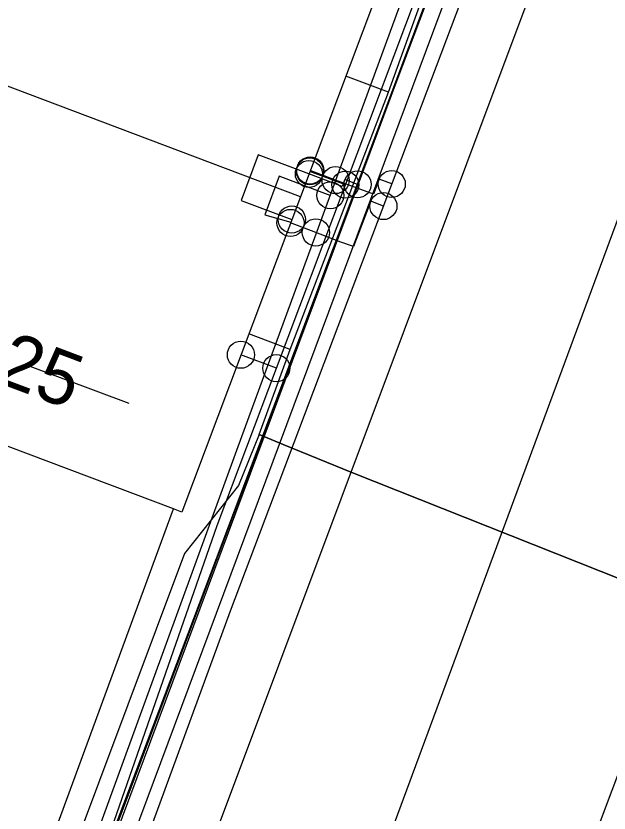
# Model space of a CAD drawing. Extents: x 192672 to 192910, y 446344 to 446512.
# Drawn here: x 192741.13 to 192752.08, y 446417.71 to 446432.42 of the extents above; entities that cross this region are included whole.
import ezdxf

# ---------------------------------------------------------------- set-up
doc = ezdxf.new("R2010")
doc.units = 0
for name, color, linetype in [('B-OI-KL-()_PUNTVANLEVERING_WATER-S', 7, 'Continuous'), ('B-OI-KL-BUISLEIDING_OLIEGASCHEMICALIEN_GASLAGEDRUK-G', 7, 'Continuous'), ('B-OI-KL-DATA-G', 7, 'Continuous'), ('B-OI-KL-DATA_GTWP-S', 7, 'Continuous'), ('B-OI-KL-DATA_KABELBED-G', 7, 'Continuous'), ('B-OI-KL-DATA_MANTELBUIS-G', 7, 'Continuous'), ('B-OI-KL-DATA_MOF-S', 7, 'Continuous'), ('B-OI-KL-ET_LS-G', 7, 'Continuous'), ('B-OI-KL-ET_LS_DELIVERYPOINT-S', 7, 'Continuous'), ('B-OI-KL-ET_LS_MOF-S', 7, 'Continuous'), ('B-OI-KL-GAS_LD_AFTAKZADEL-S', 7, 'Continuous'), ('B-OI-KL-GAS_LD_DELIVERYPOINT-S', 7, 'Continuous'), ('B-OI-KL-GAS_LD_OVERGANGSSTUK-S', 7, 'Continuous'), ('B-OI-KL-WATER-G', 7, 'Continuous'), ('B-OI-RI-RIOOLVRIJVERVAL-G', 7, 'Continuous'), ('Default', 7, 'Continuous'), ('huisnummerreeks BGT', 7, 'Continuous'), ('kant open verharding', 7, 'Continuous'), ('kant verharding', 7, 'Continuous'), ('pand op maaiveld vlak', 7, 'Continuous')]:
    doc.layers.add(name, color=color, linetype=linetype)

# ---------------------------------------------------------------- blocks, each defined once
blk = doc.blocks.new('B-OI-KL-GAS_LD_AFTAKZADEL-S')
at = {"layer": 'Default'}
blk.add_circle((0, 0), 0.25, dxfattribs=at)
blk = doc.blocks.new('B-OI-KL-GAS_LD_DELIVERYPOINT-S')
at = {"layer": 'Default'}
blk.add_circle((0, 0), 0.25, dxfattribs=at)
blk = doc.blocks.new('B-OI-KL-GAS_LD_OVERGANGSSTUK-S')
at = {"layer": 'Default'}
blk.add_circle((0, 0), 0.25, dxfattribs=at)
blk = doc.blocks.new('B-OI-KL-ET_LS_DELIVERYPOINT-S')
at = {"layer": 'Default'}
blk.add_circle((0, 0), 0.25, dxfattribs=at)
blk = doc.blocks.new('B-OI-KL-ET_LS_MOF-S')
at = {"layer": 'Default'}
blk.add_circle((0, 0), 0.25, dxfattribs=at)
blk = doc.blocks.new('B-OI-KL-()_PUNTVANLEVERING_WATER-S')
at = {"layer": 'Default'}
blk.add_circle((0, 0), 0.25, dxfattribs=at)
blk = doc.blocks.new('B-OI-KL-DATA_GTWP-S')
at = {"layer": 'Default'}
blk.add_circle((0, 0), 0.25, dxfattribs=at)
blk = doc.blocks.new('B-OI-KL-DATA_MOF-S')
at = {"layer": 'Default'}
blk.add_circle((0, 0), 0.25, dxfattribs=at)

msp = doc.modelspace()

# ---------------------------------------------------------------- linework, layer by layer
at = {"layer": 'B-OI-KL-BUISLEIDING_OLIEGASCHEMICALIEN_GASLAGEDRUK-G'}
for points in [[(192770.261, 446499.113), (192771.393, 446496.803), (192772.556, 446494.554), (192770.877, 446489.886), (192758.67, 446457.345), (192745.084, 446421.436), (192742.217, 446413.618)], [(192747.03, 446429.391), (192746.562, 446429.568)], [(192748.067, 446429.32), (192747.833, 446429.409), (192747.727, 446429.129), (192747.03, 446429.391)], [(192747.913, 446428.912), (192747.679, 446429.001), (192747.362, 446428.163), (192747.125, 446428.244), (192746.666, 446428.425)], [(192746.666, 446428.425), (192746.198, 446428.601)]]:
    msp.add_lwpolyline(points, dxfattribs=at)
at = {"layer": 'B-OI-KL-DATA-G'}
for points in [[(192768.74, 446486.807), (192749.794, 446435.599), (192742.072, 446415.039), (192739.06, 446406.841), (192720.2, 446413.77), (192719.012, 446414.118), (192696.077, 446422.823), (192683.193, 446427.673), (192678.122, 446429.261), (192675.743, 446430.156)], [(192768.74, 446486.807), (192749.794, 446435.599), (192742.072, 446415.039), (192739.06, 446406.841), (192738.917, 446406.249), (192738.75, 446405.758), (192738.438, 446405.088), (192738.002, 446404.406), (192737.543, 446403.858), (192737.067, 446403.408), (192736.56, 446403.025), (192736.06, 446402.723), (192733.684, 446396.245), (192734.518, 446394.712), (192730.316, 446383.423), (192727.316, 446375.697), (192722.899, 446364.033), (192722.458, 446362.715), (192718.077, 446351.086), (192716.68, 446347.404), (192715.968, 446345.556)], [(192768.74, 446486.807), (192749.794, 446435.599), (192742.072, 446415.039), (192739.06, 446406.841), (192738.917, 446406.249), (192738.75, 446405.758), (192738.438, 446405.088), (192738.002, 446404.406), (192737.543, 446403.858), (192737.067, 446403.408), (192736.56, 446403.025), (192736.06, 446402.723), (192733.684, 446396.245), (192734.518, 446394.712), (192730.316, 446383.423), (192727.316, 446375.697), (192722.899, 446364.033), (192722.458, 446362.715), (192718.077, 446351.086), (192716.68, 446347.404), (192715.968, 446345.556)], [(192768.74, 446486.807), (192749.794, 446435.599), (192742.072, 446415.039), (192739.06, 446406.841), (192738.917, 446406.249), (192738.75, 446405.758), (192738.438, 446405.088), (192738.002, 446404.406), (192737.543, 446403.858), (192737.067, 446403.408), (192736.56, 446403.025), (192736.06, 446402.723), (192733.684, 446396.245), (192734.518, 446394.712), (192730.316, 446383.423), (192727.316, 446375.697), (192722.899, 446364.033), (192722.458, 446362.715), (192718.077, 446351.086), (192716.68, 446347.404), (192715.968, 446345.556)], [(192768.74, 446486.807), (192749.794, 446435.599), (192742.072, 446415.039), (192739.06, 446406.841), (192738.917, 446406.249), (192738.75, 446405.758), (192738.438, 446405.088), (192738.002, 446404.406), (192737.543, 446403.858), (192737.067, 446403.408), (192736.56, 446403.025), (192736.06, 446402.723), (192733.684, 446396.245), (192734.518, 446394.712), (192730.316, 446383.423), (192727.316, 446375.697), (192722.899, 446364.033), (192722.458, 446362.715), (192718.077, 446351.086), (192716.68, 446347.404), (192715.968, 446345.556)], [(192768.74, 446486.807), (192749.794, 446435.599), (192742.072, 446415.039), (192739.06, 446406.841), (192738.917, 446406.249), (192738.75, 446405.758), (192738.438, 446405.088), (192738.002, 446404.406), (192737.543, 446403.858), (192737.067, 446403.408), (192736.56, 446403.025), (192736.06, 446402.723), (192733.684, 446396.245), (192734.518, 446394.712), (192730.316, 446383.423), (192727.316, 446375.697), (192722.899, 446364.033), (192722.458, 446362.715), (192718.077, 446351.086), (192716.68, 446347.404), (192715.968, 446345.556)], [(192768.74, 446486.807), (192749.794, 446435.599), (192742.072, 446415.039), (192739.06, 446406.841), (192738.917, 446406.249), (192738.75, 446405.758), (192738.438, 446405.088), (192738.002, 446404.406), (192737.543, 446403.858), (192737.067, 446403.408), (192736.56, 446403.025), (192736.06, 446402.723), (192733.684, 446396.245), (192734.518, 446394.712), (192730.316, 446383.423), (192727.316, 446375.697), (192722.899, 446364.033), (192722.458, 446362.715), (192718.077, 446351.086), (192716.68, 446347.404), (192715.968, 446345.556)], [(192768.74, 446486.807), (192749.794, 446435.599), (192742.072, 446415.039), (192739.06, 446406.841), (192738.917, 446406.249), (192738.75, 446405.758), (192738.438, 446405.088), (192738.002, 446404.406), (192737.543, 446403.858), (192737.067, 446403.408), (192736.56, 446403.025), (192736.06, 446402.723), (192733.684, 446396.245), (192734.518, 446394.712), (192730.316, 446383.423), (192727.316, 446375.697), (192722.899, 446364.033), (192722.458, 446362.715), (192718.077, 446351.086), (192716.68, 446347.404), (192715.968, 446345.556)], [(192768.74, 446486.807), (192749.794, 446435.599), (192742.072, 446415.039), (192739.06, 446406.841), (192738.917, 446406.249), (192738.75, 446405.758), (192738.438, 446405.088), (192738.002, 446404.406), (192737.543, 446403.858), (192737.067, 446403.408), (192736.56, 446403.025), (192736.06, 446402.723), (192733.684, 446396.245), (192734.518, 446394.712), (192730.316, 446383.423), (192727.316, 446375.697), (192722.899, 446364.033), (192722.458, 446362.715), (192718.077, 446351.086), (192716.68, 446347.404), (192715.968, 446345.556)], [(192768.74, 446486.807), (192749.794, 446435.599), (192742.072, 446415.039), (192739.06, 446406.841), (192738.917, 446406.249), (192738.75, 446405.758), (192738.438, 446405.088), (192738.002, 446404.406), (192737.543, 446403.858), (192737.067, 446403.408), (192736.56, 446403.025), (192736.06, 446402.723), (192733.684, 446396.245), (192734.518, 446394.712), (192730.316, 446383.423), (192727.316, 446375.697), (192722.899, 446364.033), (192722.458, 446362.715), (192718.077, 446351.086), (192716.68, 446347.404), (192715.968, 446345.556)], [(192768.74, 446486.807), (192749.794, 446435.599), (192742.072, 446415.039), (192739.06, 446406.841), (192738.917, 446406.249), (192738.75, 446405.758), (192738.438, 446405.088), (192738.002, 446404.406), (192737.543, 446403.858), (192737.067, 446403.408), (192736.56, 446403.025), (192736.06, 446402.723), (192733.684, 446396.245), (192734.518, 446394.712), (192730.316, 446383.423), (192727.316, 446375.697), (192722.899, 446364.033), (192722.458, 446362.715), (192718.077, 446351.086), (192716.68, 446347.404), (192715.968, 446345.556)], [(192768.74, 446486.807), (192749.794, 446435.599), (192742.072, 446415.039), (192739.06, 446406.841), (192738.917, 446406.249), (192738.75, 446405.758), (192738.438, 446405.088), (192738.002, 446404.406), (192737.543, 446403.858), (192737.067, 446403.408), (192736.56, 446403.025), (192736.06, 446402.723), (192733.684, 446396.245), (192734.518, 446394.712), (192730.316, 446383.423), (192727.316, 446375.697), (192722.899, 446364.033), (192722.458, 446362.715), (192718.077, 446351.086), (192716.68, 446347.404), (192715.968, 446345.556)], [(192768.74, 446486.807), (192749.794, 446435.599), (192742.072, 446415.039), (192739.06, 446406.841), (192738.917, 446406.249), (192738.75, 446405.758), (192738.438, 446405.088), (192738.002, 446404.406), (192737.543, 446403.858), (192737.067, 446403.408), (192736.56, 446403.025), (192736.06, 446402.723), (192733.684, 446396.245), (192734.518, 446394.712), (192730.316, 446383.423), (192727.316, 446375.697), (192722.899, 446364.033), (192722.458, 446362.715), (192718.077, 446351.086), (192716.68, 446347.404), (192715.968, 446345.556)], [(192768.74, 446486.807), (192749.794, 446435.599), (192742.072, 446415.039), (192739.06, 446406.841), (192738.917, 446406.249), (192738.75, 446405.758), (192738.438, 446405.088), (192738.002, 446404.406), (192737.543, 446403.858), (192737.067, 446403.408), (192736.56, 446403.025), (192736.06, 446402.723), (192733.684, 446396.245), (192734.518, 446394.712), (192730.316, 446383.423), (192727.316, 446375.697), (192722.899, 446364.033), (192722.458, 446362.715), (192718.077, 446351.086), (192716.68, 446347.404), (192715.968, 446345.556)], [(192768.74, 446486.807), (192749.794, 446435.599), (192742.072, 446415.039), (192739.06, 446406.841), (192738.917, 446406.249), (192738.75, 446405.758), (192738.438, 446405.088), (192738.002, 446404.406), (192737.543, 446403.858), (192737.067, 446403.408), (192736.56, 446403.025), (192736.06, 446402.723), (192733.684, 446396.245), (192734.518, 446394.712), (192730.316, 446383.423), (192727.316, 446375.697), (192722.899, 446364.033), (192722.458, 446362.715), (192718.077, 446351.086), (192716.68, 446347.404), (192715.968, 446345.556)], [(192768.74, 446486.807), (192749.794, 446435.599), (192742.072, 446415.039), (192739.06, 446406.841), (192738.917, 446406.249), (192738.75, 446405.758), (192738.438, 446405.088), (192738.002, 446404.406), (192737.543, 446403.858), (192737.067, 446403.408), (192736.56, 446403.025), (192736.06, 446402.723), (192733.684, 446396.245), (192734.518, 446394.712), (192730.316, 446383.423), (192727.316, 446375.697), (192722.899, 446364.033), (192722.458, 446362.715), (192718.077, 446351.086), (192716.68, 446347.404), (192715.968, 446345.556)], [(192733.785, 446392.743), (192734.518, 446394.712), (192733.684, 446396.245), (192736.06, 446402.723), (192736.56, 446403.025), (192737.067, 446403.408), (192737.543, 446403.858), (192738.002, 446404.406), (192738.438, 446405.088), (192738.75, 446405.758), (192738.917, 446406.249), (192739.06, 446406.841), (192742.072, 446415.039), (192749.794, 446435.599), (192768.74, 446486.807)], [(192748.006, 446431.014), (192749.629, 446435.53), (192749.763, 446436.782)], [(192745.236, 446436.264), (192745.276, 446436.371), (192749.491, 446434.791), (192742.072, 446415.039), (192739.06, 446406.841), (192720.2, 446413.77), (192719.012, 446414.118), (192696.077, 446422.823), (192683.193, 446427.673), (192678.122, 446429.261), (192675.743, 446430.156)], [(192745.236, 446436.264), (192745.276, 446436.371), (192749.491, 446434.791), (192742.072, 446415.039), (192739.06, 446406.841), (192725.038, 446411.993)], [(192748.006, 446431.014), (192747.219, 446431.311)], [(192746.189, 446426.268), (192748.006, 446431.014)], [(192746.189, 446426.268), (192745.428, 446426.555)], [(192745.619, 446424.697), (192746.189, 446426.268)], [(192741.384, 446425.959), (192743.212, 446425.276)], [(192745.619, 446424.697), (192745.237, 446423.754), (192744.239, 446422.5), (192741.607, 446415.471), (192741.284, 446414.993), (192740.849, 446413.811), (192740.953, 446413.129), (192738.997, 446408.143), (192738.51, 446407.367), (192737.667, 446407.73)], [(192753.019, 446415.296), (192753.389, 446416.428), (192755.111, 446420.888), (192753.608, 446421.506), (192747.333, 446423.998), (192746.061, 446424.511), (192745.619, 446424.697), (192745.237, 446423.754), (192744.239, 446422.5), (192741.607, 446415.471), (192741.284, 446414.993), (192740.849, 446413.811), (192740.953, 446413.129), (192738.997, 446408.143), (192738.51, 446407.367), (192737.667, 446407.73)], [(192745.619, 446424.697), (192746.061, 446424.511), (192747.333, 446423.998), (192753.608, 446421.506), (192755.111, 446420.888)]]:
    msp.add_lwpolyline(points, dxfattribs=at)
at = {"layer": 'B-OI-KL-DATA_KABELBED-G'}
for points in [[(192741.713, 446414.036), (192744.844, 446423.02), (192745.937, 446425.921), (192747.211, 446429.306), (192749.226, 446434.655), (192749.571, 446435.71), (192751.005, 446439.535), (192753.868, 446447.173), (192756.275, 446453.596), (192757.334, 446456.42), (192758.244, 446458.849)], [(192739.06, 446406.841), (192749.491, 446434.791)], [(192747.211, 446429.306), (192746.556, 446429.552)], [(192745.937, 446425.921), (192745.282, 446426.169)], [(192741.384, 446425.959), (192743.212, 446425.276)]]:
    msp.add_lwpolyline(points, dxfattribs=at)
at = {"layer": 'B-OI-KL-DATA_MANTELBUIS-G'}
msp.add_lwpolyline([(192747.205, 446424.047), (192753.608, 446421.506)], dxfattribs=at)
at = {"layer": 'B-OI-KL-ET_LS-G'}
for points in [[(192737.952, 446406.43), (192738.358, 446406.675), (192738.717, 446406.983), (192739.022, 446407.347), (192739.262, 446407.755), (192739.381, 446408.001), (192760.347, 446463.479), (192768.676, 446485.881)], [(192746.538, 446429.504), (192745.602, 446429.856), (192745.286, 446429.017), (192746.222, 446428.664)], [(192747.436, 446429.312), (192747.202, 446429.401), (192747.153, 446429.272), (192746.538, 446429.504)]]:
    msp.add_lwpolyline(points, dxfattribs=at)
at = {"layer": 'B-OI-KL-WATER-G'}
for points in [[(192741.742, 446414.91), (192745.233, 446424.477), (192759.645, 446463.744), (192768.2, 446486.375), (192771.087, 446494.09), (192771.168, 446494.386), (192771.221, 446494.601), (192771.269, 446494.816), (192771.346, 446495.222)], [(192746.456, 446429.287), (192745.989, 446429.463), (192745.723, 446428.753), (192746.204, 446428.616)], [(192746.933, 446429.109), (192746.456, 446429.287)]]:
    msp.add_lwpolyline(points, dxfattribs=at)
at = {"layer": 'B-OI-RI-RIOOLVRIJVERVAL-G'}
msp.add_lwpolyline([(192740.63, 446397.31), (192759.86, 446449.26)], dxfattribs=at)
at = {"layer": 'kant open verharding'}
msp.add_line((192741.127, 446415.414), (192744.037, 446423.324), dxfattribs=at)
at = {"layer": 'kant verharding'}
for p, q in [((192751.119, 446434.16), (192741.115, 446407.463)), ((192750.151, 446412.873), (192753.421, 446421.556))]:
    msp.add_line(p, q, dxfattribs=at)
msp.add_lwpolyline([(192739.919, 446408.255), (192749.62, 446434.241), (192750.477, 446433.889)], dxfattribs=at)
at = {"layer": 'pand op maaiveld vlak'}
for p, q in [((192748.571, 446434.902), (192746.38, 446429.084)), ((192746.38, 446429.084), (192738.567, 446432.027))]:
    msp.add_line(p, q, dxfattribs=at)
for points in [[(192744.037, 446423.324), (192736.376, 446426.21), (192738.567, 446432.027)], [(192746.38, 446429.084), (192744.189, 446423.267), (192744.037, 446423.324)]]:
    msp.add_lwpolyline(points, dxfattribs=at)

# ---------------------------------------------------------------- block references
at = {"layer": 'B-OI-KL-()_PUNTVANLEVERING_WATER-S'}
msp.add_blockref('B-OI-KL-()_PUNTVANLEVERING_WATER-S', (192746.933, 446429.109), dxfattribs=at)
at = {"layer": 'B-OI-KL-DATA_GTWP-S'}
for p in [(192746.556, 446429.552), (192747.211, 446429.306), (192745.282, 446426.169), (192745.937, 446425.921)]:
    msp.add_blockref('B-OI-KL-DATA_GTWP-S', p, dxfattribs=at)
at = {"layer": 'B-OI-KL-DATA_MOF-S'}
for p in [(192747.211, 446429.306), (192745.937, 446425.921)]:
    msp.add_blockref('B-OI-KL-DATA_MOF-S', p, dxfattribs=at)
at = {"layer": 'B-OI-KL-ET_LS_DELIVERYPOINT-S'}
for p in [(192746.538, 446429.504), (192746.222, 446428.664)]:
    msp.add_blockref('B-OI-KL-ET_LS_DELIVERYPOINT-S', p, dxfattribs=at)
at = {"layer": 'B-OI-KL-ET_LS_MOF-S'}
msp.add_blockref('B-OI-KL-ET_LS_MOF-S', (192747.436, 446429.312), dxfattribs=at)
at = {"layer": 'B-OI-KL-GAS_LD_AFTAKZADEL-S'}
for p in [(192748.067, 446429.32), (192747.913, 446428.912)]:
    msp.add_blockref('B-OI-KL-GAS_LD_AFTAKZADEL-S', p, dxfattribs=at)
at = {"layer": 'B-OI-KL-GAS_LD_DELIVERYPOINT-S'}
for p in [(192746.562, 446429.568), (192746.198, 446428.601)]:
    msp.add_blockref('B-OI-KL-GAS_LD_DELIVERYPOINT-S', p, dxfattribs=at)
at = {"layer": 'B-OI-KL-GAS_LD_OVERGANGSSTUK-S'}
for p in [(192747.03, 446429.391), (192746.666, 446428.425)]:
    msp.add_blockref('B-OI-KL-GAS_LD_OVERGANGSSTUK-S', p, dxfattribs=at)

# ---------------------------------------------------------------- texts
at = {"layer": 'huisnummerreeks BGT'}
msp.add_text('125', height=1, rotation=339.4, dxfattribs=at).set_placement((192740.026, 446425.941))

doc.saveas('drawing.dxf')
